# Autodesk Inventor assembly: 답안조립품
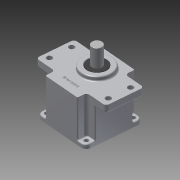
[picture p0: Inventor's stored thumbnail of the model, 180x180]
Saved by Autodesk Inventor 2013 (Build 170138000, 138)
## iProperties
Created: 2015-07
Part Number: 답안조립품
Document SubType Name: Assembly
Designer: user
Author: user
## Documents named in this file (12)
- C:\Users\user\Desktop\450734V1022\답안조립품.iam
- C:\Users\user\Desktop\450734V1022\메인축.ipt
- C:\Users\user\Desktop\450734V1022\베어링 608.ipt
- 베어링 608.ipt
- C:\Users\user\Desktop\450734V1022\베어링 6003.ipt
- 베어링 6003.ipt
- C:\Users\user\Desktop\450734V1022\서브축.ipt
- C:\Users\user\Desktop\450734V1022\본체.ipt
- C:\Users\user\Desktop\450734V1022\커버.ipt
- C:\Users\user\Desktop\450734V1022\M4x0.5x16.ipt
- C:\Users\user\Desktop\450734V1022\오일실 17x32x8.ipt
- C:\Users\user\Desktop\450734V1022\오일실 8x22x7.ipt
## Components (4 placed, 1 different names)
1. M4x0.5x12:1
2. M4x0.5x12:2
3. M4x0.5x12:3
4. M4x0.5x12:4
